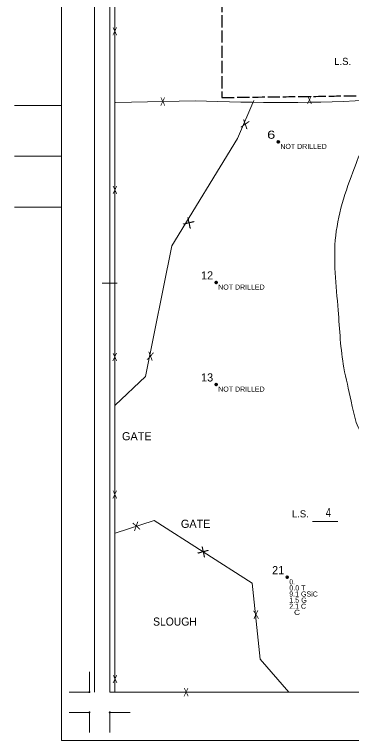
# Model space of a CAD drawing. Extents: x -496 to 480, y -450 to 700.
# Drawn here: x -496 to -165, y -450 to 264 of the extents above; entities that cross this region are included whole.
import ezdxf
from ezdxf.enums import TextEntityAlignment as Align

# ---------------------------------------------------------------- set-up
doc = ezdxf.new("R2010")
doc.units = 0
doc.header["$LTSCALE"] = 2
doc.header["$PDMODE"] = 32
doc.header["$PDSIZE"] = 1
doc.linetypes.add('LONG_DASHED', pattern=[7.5, 6, -1.5])
for name, color, linetype, lineweight in [('1', 7, 'Continuous', 13), ('2', 7, 'Continuous', 35), ('3', 7, 'Continuous', 13), ('4', 7, 'Continuous', 25)]:
    doc.layers.add(name, color=color, linetype=linetype, lineweight=lineweight)

msp = doc.modelspace()

# ---------------------------------------------------------------- linework, layer by layer
at = {"layer": '1'}
for p, q in [((-402.391, 402.339), (-402.391, -402.333)), ((-450.017, 174.973), (-496.057, 174.973)), ((-450.017, 124.973), (-496.057, 124.973)), ((-450.017, 74.973), (-496.057, 74.973)), ((-395.017, -0.027), (-410.017, -0.027)), ((-202.998, -234.618), (-177.998, -234.618)), ((-422.391, -402.333), (-422.391, -382.333)), ((-422.391, -402.333), (-442.391, -402.333)), ((-402.391, -402.333), (402.281, -402.333)), ((-422.391, -422.333), (-442.391, -422.333)), ((-422.391, -422.333), (-422.391, -442.333)), ((-402.391, -422.333), (-402.391, -442.333)), ((-450.017, -450.027), (449.983, -450.027))]:
    msp.add_line(p, q, dxfattribs=at)
for points in [[(449.983, -450.027), (449.983, 399.973), (449.983, 699.973), (-450.017, 699.973), (-450.017, 49.973), (-450.017, -450.027)], [(-402.391, -422.333), (-382.391, -422.333), (-402.391, -422.333)]]:
    msp.add_lwpolyline(points, dxfattribs=at)
for p in [(-422.391, -402.333), (-422.391, -422.333), (-402.391, -422.333)]:
    msp.add_point(p, dxfattribs=at)
at = {"layer": '2', "linetype": 'LONG_DASHED', "lineweight": 25}
msp.add_line((-292.391, 398.739), (-292.094, 182.712), dxfattribs=at)
at = {"layer": '2'}
for centre in [(-236.67, 139.137), (-297.771, 0.687), (-297.771, -99.726), (-227.901, -289.395)]:
    msp.add_circle(centre, 1, dxfattribs=at)
at = {"layer": '2', "linetype": 'LONG_DASHED', "lineweight": 25}
msp.add_spline([(-292.094, 182.712), (-228.927, 183.56), (-186.721, 184.126), (-147.914, 183.843), (-134.034, 184.692), (-129.219, 187.521), (-119.588, 202.517), (-115.056, 211.571), (-107.124, 218.078), (-74.266, 239.298)], degree=3, dxfattribs=at)
at = {"layer": '2'}
for points in [[(-236.681, 140.024), (-235.95, 139.62), (-235.799, 138.771), (-236.484, 138.243), (-237.293, 138.474), (-237.579, 139.232), (-237.332, 139.794), (-236.759, 139.962), (-236.085, 139.468), (-236.102, 138.726), (-236.619, 138.468), (-237.141, 138.637), (-237.366, 139.283), (-236.782, 139.749), (-236.344, 139.215), (-236.383, 138.732), (-237.012, 138.867), (-236.866, 139.502), (-236.574, 138.951)], [(-297.782, 1.574), (-297.052, 1.17), (-296.9, 0.321), (-297.585, -0.207), (-298.394, 0.024), (-298.681, 0.782), (-298.434, 1.344), (-297.861, 1.512), (-297.187, 1.018), (-297.203, 0.276), (-297.72, 0.018), (-298.243, 0.187), (-298.467, 0.833), (-297.883, 1.299), (-297.445, 0.765), (-297.484, 0.282), (-298.113, 0.417), (-297.967, 1.052), (-297.675, 0.501)], [(-297.782, -98.839), (-297.052, -99.243), (-296.9, -100.092), (-297.585, -100.62), (-298.394, -100.389), (-298.681, -99.631), (-298.434, -99.069), (-297.861, -98.901), (-297.187, -99.395), (-297.203, -100.137), (-297.72, -100.395), (-298.243, -100.226), (-298.467, -99.58), (-297.883, -99.114), (-297.445, -99.648), (-297.484, -100.131), (-298.113, -99.996), (-297.967, -99.361), (-297.675, -99.912)], [(-227.912, -288.508), (-227.182, -288.912), (-227.03, -289.761), (-227.715, -290.289), (-228.524, -290.058), (-228.811, -289.3), (-228.564, -288.738), (-227.991, -288.57), (-227.317, -289.064), (-227.333, -289.806), (-227.85, -290.064), (-228.373, -289.895), (-228.597, -289.249), (-228.013, -288.783), (-227.575, -289.317), (-227.614, -289.8), (-228.243, -289.665), (-228.097, -289.03), (-227.805, -289.581)]]:
    msp.add_spline(points, degree=3, dxfattribs=at)
at = {"layer": '3'}
for p, q in [((-417.391, 402.339), (-417.391, -402.333)), ((-397.391, 402.339), (-397.391, -402.333)), ((-318.462, 179.332), (-396.757, 177.99)), ((-397.389, -402.333), (402.281, -402.333))]:
    msp.add_line(p, q, dxfattribs=at)
for points in [[(-260.853, 179.798), (-276.844, 142.298), (-341.502, 36.743), (-367.226, -91.729), (-397.14, -119.948)], [(-397.122, -245.896), (-358.883, -233.396), (-262.244, -295.201), (-254.674, -370.122), (-226.18, -402.333)]]:
    msp.add_lwpolyline(points, dxfattribs=at)
for points in [[(402.334, 128.248), (383.156, 141.817), (361.58, 167.359), (316.03, 204.874), (294.455, 212.058), (261.691, 224.828), (175.387, 224.828), (143.423, 227.223), (125.043, 232.012), (105.066, 233.608), (72.302, 239.196), (51.525, 250.37), (31.548, 256.756), (-6.81, 256.756), (-62.747, 242.389), (-112.292, 210.461), (-141.859, 162.57), (-160.239, 117.872), (-180.217, 46.833), (-177.819, -26.6), (-172.225, -83.271), (-165.033, -115.996), (-149.85, -153.511), (-130.672, -161.493), (-98.707, -171.071), (-74.734, -182.245), (-33.18, -199.806), (16.364, -206.191), (58.717, -207.787), (95.476, -213.375), (128.24, -226.944), (149.017, -239.715), (176.985, -270.046), (196.164, -292.395), (211.347, -300.377), (239.316, -307.56), (295.735, -304.937)], [(423.111, 180.13), (421.513, 89.935), (195.365, 89.137), (172.99, 133.037), (157.008, 172.148), (145.021, 187.314), (119.45, 191.305), (100.271, 195.296), (77.097, 224.828), (60.315, 234.407), (35.543, 236.003), (16.364, 225.627), (-62.747, 202.479), (-113.89, 184.121), (-138.663, 180.928), (-318.462, 179.332)]]:
    msp.add_spline(points, degree=3, dxfattribs=at)

# ---------------------------------------------------------------- texts
at = {"layer": '1'}
for p in [(-173.44, 214.794), (-215.009, -230.48)]:
    msp.add_text('L.S.', height=7, dxfattribs=at).set_placement(p, align=Align.CENTER)
at = {"layer": '1', "width": 0.75}
msp.add_text('4', height=8.89, dxfattribs=at).set_placement((-187.46, -230.008), align=Align.CENTER)
at = {"layer": '2', "width": 1.35}
msp.add_text('  6', height=8, dxfattribs=at).set_placement((-239.67, 142.137), align=Align.RIGHT)
at = {"layer": '2'}
for s, p in [('NOT DRILLED', (-234.67, 132.137)), ('NOT DRILLED', (-295.771, -6.313)), ('NOT DRILLED', (-295.771, -106.726)), ('9.1 GSiC   ', (-225.901, -308.395)), ('2.1 C      ', (-225.901, -320.395))]:
    msp.add_text(s, height=5, dxfattribs=at).set_placement(p)
for s, p in [(' 12', (-300.772, 3.687)), (' 13', (-300.772, -96.726)), (' 21', (-230.902, -286.395))]:
    msp.add_text(s, height=8, dxfattribs=at).set_placement(p, align=Align.RIGHT)
for s, width, p in [('0.         ', 0.95, (-225.901, -296.395)), ('0.0 T      ', 1.05, (-225.901, -302.395)), ('1.5 G      ', 1.05, (-225.901, -314.395)), ('  C        ', 1.25, (-225.901, -326.395))]:
    msp.add_text(s, height=5, dxfattribs=dict(at, width=width)).set_placement(p)
at = {"layer": '3', "width": 0.7}
for p in [(-397.466, 243.865), (-350.319, 174.792), (-206.076, 176.278), (-397.354, 87.646), (-397.497, -76.572), (-397.464, -212.037), (-397.258, -393.563), (-327.344, -406.424)]:
    msp.add_text('X', height=8, dxfattribs=at).set_placement(p, align=Align.CENTER)
at = {"layer": '3'}
for rotation, width, p in [(341.795, 1.1, (-270.531, 152.566)), (327.485, 1.45, (-326.75, 55.962)), (349.552, 0.9, (-363.179, -75.798)), (328.701, 1.4, (-312.654, -267.757)), (3.827, 0.8, (-258.417, -330.204))]:
    msp.add_text('X', height=8, rotation=rotation, dxfattribs=dict(at, width=width)).set_placement(p, align=Align.CENTER)
msp.add_text('X', height=8, rotation=14.446, dxfattribs=at).set_placement((-375.376, -243.009), align=Align.CENTER)
at = {"layer": '4'}
for p in [(-375.841, -154.6), (-317.923, -240.785)]:
    msp.add_text('GATE', height=8, dxfattribs=at).set_placement(p, align=Align.CENTER)
at = {"layer": '4', "width": 0.95}
msp.add_text('SLOUGH', height=8, dxfattribs=at).set_placement((-338.342, -336.999), align=Align.CENTER)

doc.saveas('drawing.dxf')
